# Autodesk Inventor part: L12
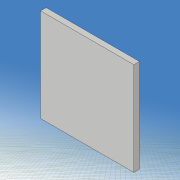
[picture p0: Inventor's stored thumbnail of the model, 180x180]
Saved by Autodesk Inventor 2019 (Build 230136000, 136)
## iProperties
Created: 2021-05
Part Number: L12
Material: 一般
Document SubType Name: Modeling
Designer: kikut
Density: 1 g/cm^3
Appearance: 既定
Mass: 0.00934248 g
Surface Area: 0.426451 cm^2
Volume: 0.00934248 cm^3
Author: kikut
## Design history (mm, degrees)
sketch "スケッチ1"
  geometry: L1 (80, 60)-(-80, 60); L2 (-80, 60)-(-80, -60); L3 (-80, -60)-(80, -60); L4 (80, -60)-(80, 60); L5 (80, 60)-(-80, -60); L6 (-80, 60)-(80, -60); 1 further point
  constraints: 12 end point, 2 midpoint, 2 parallel, 1 horizontal, 1 perpendicular
  dimensions: "d0" = 160 distance of L2.end L3.end; "d1" = 120 distance of L1.end L2.end
extrude "押し出し1" new body sketch "スケッチ1" stored distance "d2" = 0.6; taper "d3" = 0 deg
sketch "スケッチ2"
  geometry: L1 (-140, 0)-(140, 0) reference; L2 (0, -54)-(20, -30); L3 (0, 54)-(20, 30); L4 (0, -3)-(6.514, -3); L5 (6.514, -3)-(16, -6); L6 (16, -6)-(24, -3); L7 (24, -3)-(33.716, -3); L8 (0, 3)-(6.514, 3); L9 (6.514, 3)-(16, 6); L10 (16, 6)-(24, 3); L11 (24, 3)-(33.716, 3); L12 (0, -98)-(0, 98) reference; L13 (-100, -70)-(100, -70); L14 (100, -70)-(100, 70); L15 (100, 70)-(-100, 70); L16 (-100, 70)-(-100, -70); L17 (-100, -70)-(100, 70); L18 (100, -70)-(-100, 70); A1 r 60 centre (54.312, 28.5) between (0, 54) and (0, 3); A2 r 60 centre (54.312, -28.5) between (0, -3) and (0, -54); A3 r 18.111 centre (18, -12) between (20, -30) and (33.716, -3); A4 r 18.111 centre (18, 12) between (33.716, 3) and (20, 30); 1 further point
  constraints: 32 end point, 8 point on circle, 8 symmetric about line, 4 centre point, 3 horizontal, 2 collinear, 2 midpoint, 2 parallel, 1 perpendicular
  dimensions: "d5" = 60 radius of A1; "d6" = 6 distance of L8.start L4.start; "d7" = 108 distance of L3.start L2.start; "d8" = 0 horizontal distance of L3.start L8.start; "d9" = 60 distance of L3.end L2.end; "d10" = 0 horizontal distance of point (0, 0) L3.start; "d11" = 20 horizontal distance of L3.start L3.end; "d12" = 24 distance of A4.centre A3.centre; "d13" = 6 distance of L11.end L7.end; "d14" = 12 distance of L9.end L5.end; "d15" = 16 distance from line of L12 L5.end; "d16" = 24 distance from line of L6.end L12; "d17" = 200 distance of L14.end L15.end; "d18" = 140 distance of L15.end L13.start; "d30" = 18 distance from line of L12 A4.centre
extrude "押し出し2" cut sketch "スケッチ2" stored distance "d19" = 10; taper "d20" = 0 deg
sketch "スケッチ3"
  geometry: L1 (49.705, -17.97)-(33.948, -15.191); L2 (33.948, -15.191)-(34.295, -13.222); L3 (34.295, -13.222)-(50.052, -16); L4 (50.052, -16)-(49.705, -17.97); L5 (49.705, -17.97)-(34.295, -13.222); L6 (33.948, -15.191)-(50.052, -16); L7 (50.052, 16)-(34.295, 13.222); L8 (34.295, 13.222)-(33.948, 15.191); L9 (33.948, 15.191)-(49.705, 17.97); L10 (49.705, 17.97)-(50.052, 16); L11 (50.052, 16)-(33.948, 15.191); L12 (34.295, 13.222)-(49.705, 17.97); L13 (-112, 0)-(112, 0) reference; L14 (0, -84)-(0, 84) reference; 3 further points
  constraints: 24 end point, 4 midpoint, 4 parallel, 2 perpendicular, 2 symmetric about line
  dimensions: "d21" = 2 distance of L3.end L1.start; "d22" = 2 distance of L9.end L7.start; "d23" = 16 distance of L8.end L9.end; "d24" = 42 distance from line of L14 point (42, 15.596); "d26" = 10 deg angle of L7 L13; "d62" = 16 distance from line of L3.end L13
extrude "押し出し3" join sketch "スケッチ3" distance "d27" = 0.6; taper "d28" = 0 deg
fillet "フィレット1" dims "d31" = 2
fillet "フィレット2" dims "d32" = 1
sketch "スケッチ7"
  geometry: L1 (-20, 60)-(80, 60); L2 (80, 60)-(80, -60); L3 (80, -60)-(-20, -60); L4 (-20, -60)-(-20, 60); L5 (0, -82.207)-(0, 85.793) reference; L6 (-40, 0)-(100, 0) reference; L7 (0, -20)-(10, -20); L8 (10, -20)-(10, -30); L9 (10, -30)-(0, -30); L10 (0, -30)-(0, -20); 1 further point
  constraints: 16 end point, 4 parallel, 2 horizontal, 2 perpendicular, 1 other
  dimensions: "d80" = 120 distance of L3.end L1.start; "d81" = 20 distance between parallel lines of L5 L4; "d82" = 100 distance of L1.start L1.end; "d84" = 10 distance of L8.end L9.end; "d85" = 10 distance of L7.end L8.end; "d86" = 20 distance between parallel lines of L4 L10; "d90" = 20 distance between parallel lines of L7 L6
extrude "押し出し5" cut sketch "スケッチ7" stored distance "d87" = 10; taper "d88" = 0 deg
node "ソリッド1"
